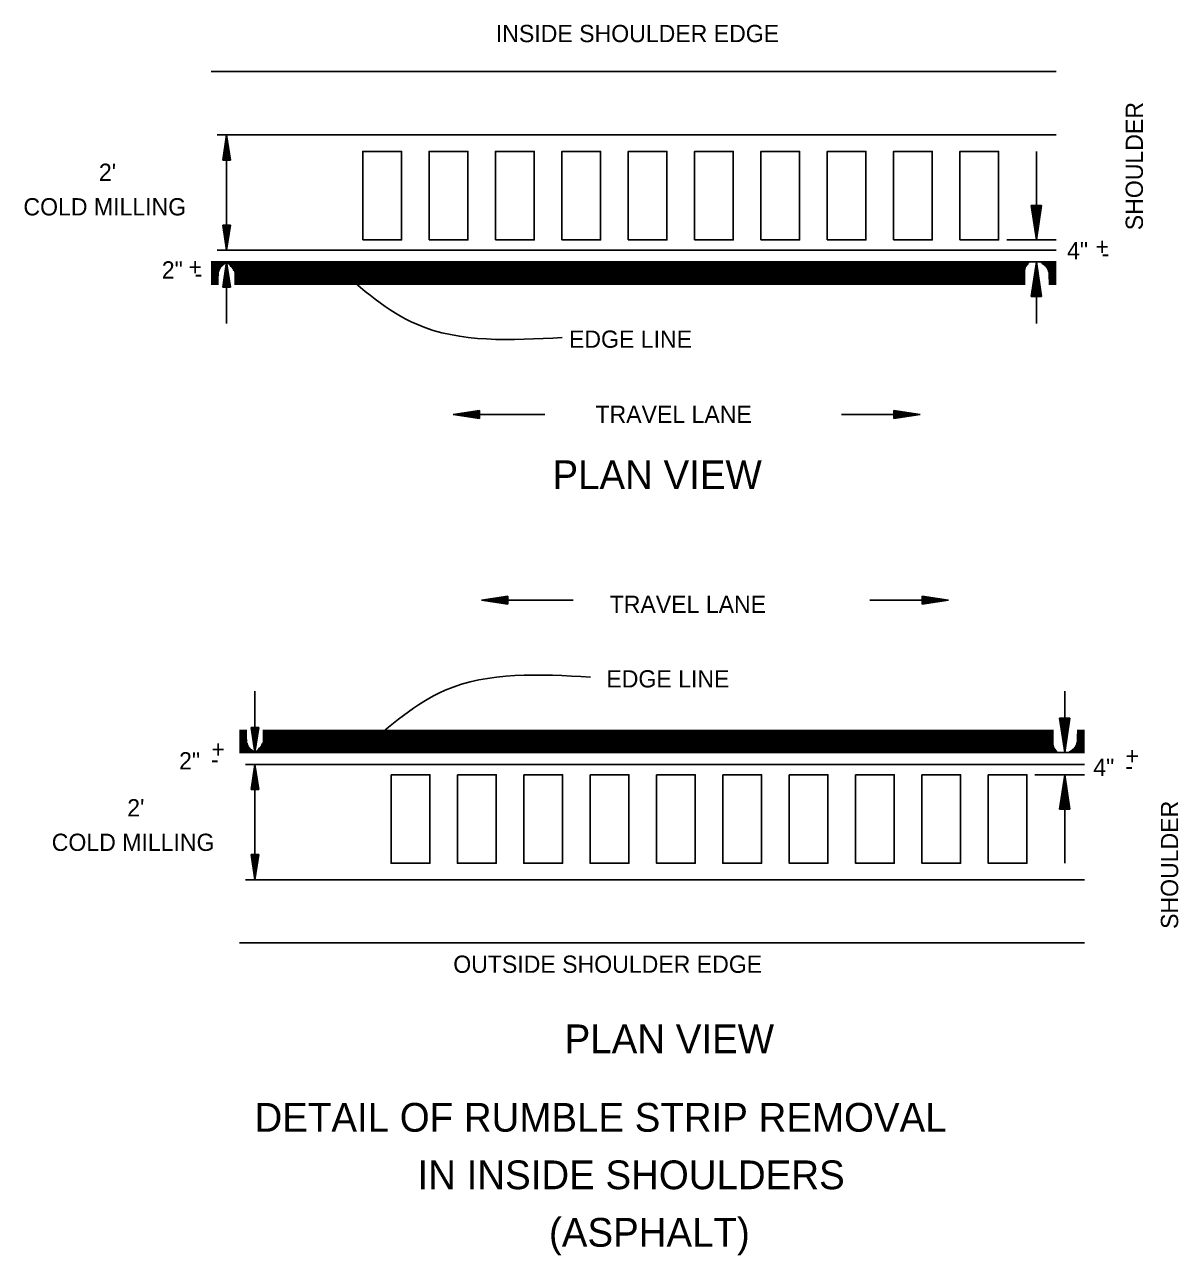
# Model space of a CAD drawing. Extents: x -2842 to 2681, y -2139 to 474.
# Drawn here: x 1152.1 to 1553.5, y -1459 to -1030.9 of the extents above; entities that cross this region are included whole.
import ezdxf

# ---------------------------------------------------------------- set-up
doc = ezdxf.new("R2010")
doc.units = 0
for name, color, linetype in [('B_Copy In', 7, 'Continuous'), ('R_Border', 7, 'Continuous'), ('R_Border Notes', 7, 'Continuous')]:
    doc.layers.add(name, color=color, linetype=linetype)

msp = doc.modelspace()

# ---------------------------------------------------------------- linework, layer by layer
at = {"layer": 'B_Copy In'}
for p, q in [((1216.98, -1047.3), (1510.94, -1047.3)), ((1246.68, -1069.29), (1510.94, -1069.29)), ((1477.46, -1075.05), (1477.46, -1105.81)), ((1246.68, -1109.41), (1510.94, -1109.41)), ((1216.98, -1113.49), (1510.94, -1113.49)), ((1222.31, -1113.72), (1216.98, -1113.72)), ((1221.94, -1113.95), (1216.98, -1113.95)), ((1221.63, -1114.2), (1216.98, -1114.2)), ((1221.25, -1114.44), (1216.98, -1114.44)), ((1221.01, -1114.68), (1216.98, -1114.68)), ((1220.69, -1114.91), (1216.98, -1114.91)), ((1220.52, -1115.17), (1216.98, -1115.17)), ((1220.35, -1115.41), (1216.98, -1115.41)), ((1220.2, -1115.65), (1216.98, -1115.65)), ((1220.13, -1115.89), (1216.98, -1115.89)), ((1220.02, -1116.12), (1216.98, -1116.12)), ((1219.89, -1116.37), (1216.98, -1116.37)), ((1219.87, -1116.61), (1216.98, -1116.61)), ((1219.72, -1116.85), (1216.98, -1116.85)), ((1222.46, -1113.73), (1501.5, -1113.73)), ((1222.79, -1113.97), (1501.28, -1113.97)), ((1223.19, -1114.21), (1501.16, -1114.21)), ((1223.38, -1114.45), (1501, -1114.45)), ((1223.52, -1114.69), (1500.75, -1114.69)), ((1223.65, -1114.92), (1500.58, -1114.92)), ((1223.96, -1115.18), (1500.41, -1115.18)), ((1224.19, -1115.42), (1500.36, -1115.42)), ((1224.36, -1115.66), (1500.27, -1115.66)), ((1224.51, -1115.9), (1500.27, -1115.9)), ((1224.59, -1116.13), (1500.16, -1116.13)), ((1224.69, -1116.38), (1500.14, -1116.38)), ((1224.96, -1116.62), (1500.13, -1116.62)), ((1225.03, -1116.86), (1500.13, -1116.86)), ((1505.61, -1113.73), (1510.94, -1113.73)), ((1505.98, -1113.97), (1510.94, -1113.97)), ((1506.29, -1114.21), (1510.94, -1114.21)), ((1506.67, -1114.45), (1510.94, -1114.45)), ((1506.91, -1114.69), (1510.94, -1114.69)), ((1507.24, -1114.92), (1510.94, -1114.92)), ((1507.4, -1115.18), (1510.94, -1115.18)), ((1507.57, -1115.42), (1510.94, -1115.42)), ((1507.72, -1115.66), (1510.94, -1115.66)), ((1507.79, -1115.9), (1510.94, -1115.9)), ((1507.91, -1116.13), (1510.94, -1116.13)), ((1508.03, -1116.38), (1510.94, -1116.38)), ((1508.06, -1116.62), (1510.94, -1116.62)), ((1508.21, -1116.86), (1510.94, -1116.86)), ((1219.65, -1117.09), (1216.98, -1117.09)), ((1219.65, -1117.33), (1216.98, -1117.33)), ((1219.64, -1117.58), (1216.98, -1117.58)), ((1219.64, -1117.81), (1216.98, -1117.81)), ((1219.62, -1118.05), (1216.98, -1118.05)), ((1219.61, -1118.29), (1216.98, -1118.29)), ((1219.61, -1118.53), (1216.98, -1118.53)), ((1219.6, -1118.78), (1216.98, -1118.78)), ((1219.6, -1119.02), (1216.98, -1119.02)), ((1219.59, -1119.25), (1216.98, -1119.25)), ((1219.58, -1119.49), (1216.98, -1119.49)), ((1219.58, -1119.72), (1216.98, -1119.72)), ((1219.57, -1119.98), (1216.98, -1119.98)), ((1219.57, -1120.21), (1216.98, -1120.21)), ((1219.55, -1120.46), (1216.98, -1120.46)), ((1219.54, -1120.69), (1216.98, -1120.69)), ((1219.54, -1120.93), (1216.98, -1120.93)), ((1219.53, -1121.16), (1216.98, -1121.16)), ((1225.17, -1117.1), (1500.13, -1117.1)), ((1225.17, -1117.35), (1500.13, -1117.35)), ((1225.17, -1117.59), (1500.13, -1117.59)), ((1225.17, -1117.82), (1500.13, -1117.82)), ((1225.17, -1118.06), (1500.13, -1118.06)), ((1225.17, -1118.3), (1500.13, -1118.3)), ((1225.17, -1118.55), (1500.13, -1118.55)), ((1225.17, -1118.79), (1500.13, -1118.79)), ((1225.17, -1119.03), (1500.13, -1119.03)), ((1225.17, -1119.26), (1500.13, -1119.26)), ((1225.17, -1119.5), (1500.13, -1119.5)), ((1225.17, -1119.73), (1500.13, -1119.73)), ((1225.17, -1119.99), (1500.13, -1119.99)), ((1225.17, -1120.22), (1500.13, -1120.22)), ((1225.17, -1120.47), (1500.13, -1120.47)), ((1225.17, -1120.7), (1500.13, -1120.7)), ((1225.17, -1120.95), (1500.13, -1120.95)), ((1225.17, -1121.18), (1500.13, -1121.18)), ((1508.28, -1117.1), (1510.94, -1117.1)), ((1508.28, -1117.35), (1510.94, -1117.35)), ((1508.29, -1117.59), (1510.94, -1117.59)), ((1508.29, -1117.82), (1510.94, -1117.82)), ((1508.3, -1118.06), (1510.94, -1118.06)), ((1508.31, -1118.3), (1510.94, -1118.3)), ((1508.31, -1118.55), (1510.94, -1118.55)), ((1508.32, -1118.79), (1510.94, -1118.79)), ((1508.32, -1119.03), (1510.94, -1119.03)), ((1508.33, -1119.26), (1510.94, -1119.26)), ((1508.35, -1119.5), (1510.94, -1119.5)), ((1508.35, -1119.73), (1510.94, -1119.73)), ((1508.36, -1119.99), (1510.94, -1119.99)), ((1508.36, -1120.22), (1510.94, -1120.22)), ((1508.37, -1120.47), (1510.94, -1120.47)), ((1508.38, -1120.7), (1510.94, -1120.7)), ((1508.38, -1120.95), (1510.94, -1120.95)), ((1508.39, -1121.18), (1510.94, -1121.18)), ((1229.38, -1276.44), (1226.83, -1276.44)), ((1229.39, -1276.67), (1226.83, -1276.67)), ((1229.39, -1276.92), (1226.83, -1276.92)), ((1229.4, -1277.15), (1226.83, -1277.15)), ((1229.41, -1277.4), (1226.83, -1277.4)), ((1229.41, -1277.63), (1226.83, -1277.63)), ((1229.43, -1277.89), (1226.83, -1277.89)), ((1229.43, -1278.12), (1226.83, -1278.12)), ((1229.44, -1278.36), (1226.83, -1278.36)), ((1229.45, -1278.59), (1226.83, -1278.59)), ((1229.45, -1278.83), (1226.83, -1278.83)), ((1229.46, -1279.07), (1226.83, -1279.07)), ((1229.46, -1279.32), (1226.83, -1279.32)), ((1229.47, -1279.56), (1226.83, -1279.56)), ((1235.02, -1276.43), (1509.98, -1276.43)), ((1235.02, -1276.66), (1509.98, -1276.66)), ((1235.02, -1276.9), (1509.98, -1276.9)), ((1235.02, -1277.14), (1509.98, -1277.14)), ((1235.02, -1277.39), (1509.98, -1277.39)), ((1235.02, -1277.62), (1509.98, -1277.62)), ((1235.02, -1277.87), (1509.98, -1277.87)), ((1235.02, -1278.1), (1509.98, -1278.1)), ((1235.02, -1278.35), (1509.98, -1278.35)), ((1235.02, -1278.58), (1509.98, -1278.58)), ((1235.02, -1278.82), (1509.98, -1278.82)), ((1235.02, -1279.06), (1509.98, -1279.06)), ((1235.02, -1279.3), (1509.98, -1279.3)), ((1235.02, -1279.55), (1509.98, -1279.55)), ((1518.15, -1279.55), (1520.79, -1279.55)), ((1518.16, -1279.06), (1520.79, -1279.06)), ((1518.16, -1279.3), (1520.79, -1279.3)), ((1518.17, -1278.58), (1520.79, -1278.58)), ((1518.17, -1278.82), (1520.79, -1278.82)), ((1518.18, -1278.35), (1520.79, -1278.35)), ((1518.19, -1277.87), (1520.79, -1277.87)), ((1518.19, -1278.1), (1520.79, -1278.1)), ((1518.21, -1277.39), (1520.79, -1277.39)), ((1518.21, -1277.62), (1520.79, -1277.62)), ((1518.22, -1277.14), (1520.79, -1277.14)), ((1518.23, -1276.66), (1520.79, -1276.66)), ((1518.23, -1276.9), (1520.79, -1276.9)), ((1518.24, -1276.43), (1520.79, -1276.43)), ((1229.48, -1279.8), (1226.83, -1279.8)), ((1229.48, -1280.03), (1226.83, -1280.03)), ((1229.5, -1280.27), (1226.83, -1280.27)), ((1229.5, -1280.52), (1226.83, -1280.52)), ((1229.56, -1280.76), (1226.83, -1280.76)), ((1229.71, -1281), (1226.83, -1281)), ((1229.74, -1281.24), (1226.83, -1281.24)), ((1229.86, -1281.49), (1226.83, -1281.49)), ((1229.98, -1281.72), (1226.83, -1281.72)), ((1230.05, -1281.96), (1226.83, -1281.96)), ((1230.2, -1282.2), (1226.83, -1282.2)), ((1230.37, -1282.44), (1226.83, -1282.44)), ((1230.53, -1282.7), (1226.83, -1282.7)), ((1230.86, -1282.93), (1226.83, -1282.93)), ((1231.1, -1283.17), (1226.83, -1283.17)), ((1231.48, -1283.41), (1226.83, -1283.41)), ((1231.79, -1283.65), (1226.83, -1283.65)), ((1232.16, -1283.88), (1226.83, -1283.88)), ((1232.31, -1283.87), (1511.35, -1283.87)), ((1232.64, -1283.64), (1511.13, -1283.64)), ((1233.03, -1283.4), (1511, -1283.4)), ((1233.23, -1283.16), (1510.84, -1283.16)), ((1233.37, -1282.92), (1510.6, -1282.92)), ((1233.5, -1282.68), (1510.43, -1282.68)), ((1233.8, -1282.43), (1510.25, -1282.43)), ((1234.04, -1282.19), (1510.21, -1282.19)), ((1234.21, -1281.95), (1510.12, -1281.95)), ((1234.36, -1281.7), (1510.12, -1281.7)), ((1234.44, -1281.47), (1510.01, -1281.47)), ((1234.54, -1281.23), (1509.99, -1281.23)), ((1234.81, -1280.99), (1509.98, -1280.99)), ((1234.88, -1280.75), (1509.98, -1280.75)), ((1235.02, -1279.79), (1509.98, -1279.79)), ((1235.02, -1280.02), (1509.98, -1280.02)), ((1235.02, -1280.26), (1509.98, -1280.26)), ((1235.02, -1280.5), (1509.98, -1280.5)), ((1515.46, -1283.87), (1520.79, -1283.87)), ((1515.83, -1283.64), (1520.79, -1283.64)), ((1516.14, -1283.4), (1520.79, -1283.4)), ((1516.52, -1283.16), (1520.79, -1283.16)), ((1516.76, -1282.92), (1520.79, -1282.92)), ((1517.09, -1282.68), (1520.79, -1282.68)), ((1517.25, -1282.43), (1520.79, -1282.43)), ((1517.42, -1282.19), (1520.79, -1282.19)), ((1517.57, -1281.95), (1520.79, -1281.95)), ((1517.64, -1281.7), (1520.79, -1281.7)), ((1517.76, -1281.47), (1520.79, -1281.47)), ((1517.88, -1281.23), (1520.79, -1281.23)), ((1517.91, -1280.99), (1520.79, -1280.99)), ((1518.06, -1280.75), (1520.79, -1280.75)), ((1518.12, -1280.26), (1520.79, -1280.26)), ((1518.12, -1280.5), (1520.79, -1280.5)), ((1518.14, -1279.79), (1520.79, -1279.79)), ((1518.14, -1280.02), (1520.79, -1280.02)), ((1226.83, -1284.12), (1520.79, -1284.12)), ((1256.53, -1288.2), (1520.79, -1288.2)), ((1256.53, -1328.32), (1520.79, -1328.32)), ((1226.83, -1350.3), (1520.79, -1350.3))]:
    msp.add_line(p, q, dxfattribs=at)
for points in [[(1269.76, -1105.81), (1283.23, -1105.81), (1283.23, -1075.05), (1269.76, -1075.05)], [(1292.83, -1105.81), (1306.31, -1105.81), (1306.31, -1075.05), (1292.83, -1075.05)], [(1315.91, -1105.81), (1329.39, -1105.81), (1329.39, -1075.05), (1315.91, -1075.05)], [(1338.99, -1105.81), (1352.47, -1105.81), (1352.47, -1075.05), (1338.99, -1075.05)], [(1362.07, -1105.81), (1375.54, -1105.81), (1375.54, -1075.05), (1362.07, -1075.05)], [(1385.15, -1105.81), (1398.62, -1105.81), (1398.62, -1075.05), (1385.15, -1075.05)], [(1408.22, -1105.81), (1421.7, -1105.81), (1421.7, -1075.05), (1408.22, -1075.05)], [(1431.3, -1105.81), (1444.78, -1105.81), (1444.78, -1075.05), (1431.3, -1075.05)], [(1454.38, -1105.81), (1467.86, -1105.81), (1467.86, -1075.05), (1454.38, -1075.05)], [(1477.46, -1105.81), (1490.93, -1105.81), (1490.93, -1075.05), (1477.46, -1075.05)], [(1279.6, -1291.8), (1293.08, -1291.8), (1293.08, -1322.56), (1279.6, -1322.56)], [(1302.68, -1291.8), (1316.16, -1291.8), (1316.16, -1322.56), (1302.68, -1322.56)], [(1325.76, -1291.8), (1339.24, -1291.8), (1339.24, -1322.56), (1325.76, -1322.56)], [(1348.84, -1291.8), (1362.32, -1291.8), (1362.32, -1322.56), (1348.84, -1322.56)], [(1371.92, -1291.8), (1385.39, -1291.8), (1385.39, -1322.56), (1371.92, -1322.56)], [(1394.99, -1291.8), (1408.47, -1291.8), (1408.47, -1322.56), (1394.99, -1322.56)], [(1418.07, -1291.8), (1431.55, -1291.8), (1431.55, -1322.56), (1418.07, -1322.56)], [(1441.15, -1291.8), (1454.63, -1291.8), (1454.63, -1322.56), (1441.15, -1322.56)], [(1464.23, -1291.8), (1477.7, -1291.8), (1477.7, -1322.56), (1464.23, -1322.56)], [(1487.3, -1291.8), (1500.78, -1291.8), (1500.78, -1322.56), (1487.3, -1322.56)]]:
    msp.add_lwpolyline(points, close=True, dxfattribs=at)
at = {"layer": 'R_Border Notes'}
for p, q in [((1246.68, -1069.29), (1219.15, -1069.29)), ((1221.06, -1078.06), (1222.38, -1069.29)), ((1222.38, -1069.29), (1222.38, -1109.41)), ((1223.7, -1078.06), (1222.38, -1069.29)), ((1221.27, -1078.06), (1222.38, -1070.74)), ((1221.5, -1078.06), (1222.38, -1072.27)), ((1221.73, -1078.06), (1222.38, -1073.72)), ((1223.49, -1078.06), (1222.38, -1070.74)), ((1223.26, -1078.06), (1222.38, -1072.27)), ((1223.03, -1078.06), (1222.38, -1073.72)), ((1223.7, -1078.06), (1221.06, -1078.06)), ((1221.94, -1078.06), (1222.38, -1075.22)), ((1222.17, -1078.06), (1222.38, -1076.67)), ((1222.8, -1078.06), (1222.38, -1075.22)), ((1222.59, -1078.06), (1222.38, -1076.67)), ((1504.09, -1075.05), (1504.09, -1105.81)), ((1502.29, -1093.81), (1504.09, -1105.81)), ((1502.29, -1093.81), (1505.89, -1093.81)), ((1502.59, -1093.81), (1504.09, -1103.8)), ((1502.89, -1093.81), (1504.09, -1101.75)), ((1503.19, -1093.81), (1504.09, -1099.74)), ((1503.51, -1093.81), (1504.09, -1097.71)), ((1503.81, -1093.81), (1504.09, -1095.7)), ((1505.89, -1093.81), (1504.09, -1105.81)), ((1504.66, -1093.81), (1504.09, -1097.71)), ((1505.29, -1093.81), (1504.09, -1101.75)), ((1505.59, -1093.81), (1504.09, -1103.8)), ((1504.99, -1093.81), (1504.09, -1099.74)), ((1504.36, -1093.81), (1504.09, -1095.7)), ((1221.06, -1100.64), (1222.38, -1109.41)), ((1221.06, -1100.64), (1223.7, -1100.64)), ((1221.27, -1100.64), (1222.38, -1107.96)), ((1221.5, -1100.64), (1222.38, -1106.43)), ((1221.73, -1100.64), (1222.38, -1104.98)), ((1221.96, -1100.64), (1222.38, -1103.48)), ((1222.17, -1100.64), (1222.38, -1102.03)), ((1223.7, -1100.64), (1222.38, -1109.41)), ((1222.82, -1100.64), (1222.38, -1103.48)), ((1223.26, -1100.64), (1222.38, -1106.43)), ((1223.49, -1100.64), (1222.38, -1107.96)), ((1223.03, -1100.64), (1222.38, -1104.98)), ((1222.59, -1100.64), (1222.38, -1102.03)), ((1493.73, -1105.81), (1510.94, -1105.81)), ((1246.68, -1109.41), (1219.15, -1109.41)), ((1221.06, -1122.26), (1222.38, -1113.49)), ((1221.27, -1122.26), (1222.38, -1114.95)), ((1221.5, -1122.26), (1222.38, -1116.47)), ((1223.7, -1122.26), (1222.38, -1113.49)), ((1222.38, -1113.49), (1222.38, -1134.86)), ((1223.49, -1122.26), (1222.38, -1114.95)), ((1223.26, -1122.26), (1222.38, -1116.47)), ((1502.29, -1125.49), (1504.09, -1113.49)), ((1502.59, -1125.49), (1504.09, -1115.5)), ((1505.89, -1125.49), (1504.09, -1113.49)), ((1504.09, -1113.49), (1504.09, -1134.86)), ((1505.59, -1125.49), (1504.09, -1115.5)), ((1221.73, -1122.26), (1222.38, -1117.92)), ((1221.94, -1122.26), (1222.38, -1119.42)), ((1222.17, -1122.26), (1222.38, -1120.88)), ((1223.03, -1122.26), (1222.38, -1117.92)), ((1222.8, -1122.26), (1222.38, -1119.42)), ((1222.59, -1122.26), (1222.38, -1120.88)), ((1502.89, -1125.49), (1504.09, -1117.55)), ((1503.19, -1125.49), (1504.09, -1119.56)), ((1505.29, -1125.49), (1504.09, -1117.55)), ((1504.99, -1125.49), (1504.09, -1119.56)), ((1223.7, -1122.26), (1221.06, -1122.26)), ((1505.89, -1125.49), (1502.29, -1125.49)), ((1503.51, -1125.49), (1504.09, -1121.59)), ((1503.81, -1125.49), (1504.09, -1123.6)), ((1504.66, -1125.49), (1504.09, -1121.59)), ((1504.36, -1125.49), (1504.09, -1123.6)), ((1310.37, -1165.14), (1301.14, -1166.53)), ((1301.14, -1166.53), (1333.12, -1166.53)), ((1310.37, -1167.91), (1301.14, -1166.53)), ((1310.37, -1165.37), (1302.69, -1166.53)), ((1310.37, -1167.68), (1302.69, -1166.53)), ((1310.37, -1165.61), (1304.27, -1166.53)), ((1310.37, -1167.45), (1304.27, -1166.53)), ((1310.37, -1165.84), (1305.8, -1166.53)), ((1310.37, -1167.22), (1305.8, -1166.53)), ((1310.37, -1166.08), (1307.37, -1166.53)), ((1310.37, -1166.98), (1307.37, -1166.53)), ((1310.37, -1166.31), (1308.92, -1166.53)), ((1310.37, -1166.75), (1308.92, -1166.53)), ((1310.37, -1165.14), (1310.37, -1167.91)), ((1436.31, -1166.52), (1463.68, -1166.52)), ((1454.45, -1165.13), (1463.68, -1166.52)), ((1454.45, -1167.9), (1454.45, -1165.13)), ((1454.45, -1165.36), (1462.13, -1166.52)), ((1454.45, -1165.59), (1460.55, -1166.52)), ((1454.45, -1165.82), (1459.02, -1166.52)), ((1454.45, -1166.07), (1457.45, -1166.52)), ((1454.45, -1166.3), (1455.9, -1166.52)), ((1454.45, -1167.9), (1463.68, -1166.52)), ((1454.45, -1166.97), (1457.45, -1166.52)), ((1454.45, -1167.44), (1460.55, -1166.52)), ((1454.45, -1167.67), (1462.13, -1166.52)), ((1454.45, -1167.21), (1459.02, -1166.52)), ((1454.45, -1166.74), (1455.9, -1166.52)), ((1320.22, -1229.7), (1310.99, -1231.08)), ((1310.99, -1231.08), (1342.96, -1231.08)), ((1320.22, -1232.46), (1310.99, -1231.08)), ((1320.22, -1229.93), (1312.54, -1231.08)), ((1320.22, -1232.23), (1312.54, -1231.08)), ((1320.22, -1230.16), (1314.12, -1231.08)), ((1320.22, -1232), (1314.12, -1231.08)), ((1320.22, -1230.39), (1315.65, -1231.08)), ((1320.22, -1231.77), (1315.65, -1231.08)), ((1320.22, -1230.63), (1317.22, -1231.08)), ((1320.22, -1231.53), (1317.22, -1231.08)), ((1320.22, -1230.86), (1318.77, -1231.08)), ((1320.22, -1231.3), (1318.77, -1231.08)), ((1320.22, -1232.46), (1320.22, -1229.7)), ((1446.16, -1231.09), (1473.53, -1231.09)), ((1464.3, -1229.71), (1473.53, -1231.09)), ((1464.3, -1229.71), (1464.3, -1232.48)), ((1464.3, -1229.94), (1471.98, -1231.09)), ((1464.3, -1230.17), (1470.4, -1231.09)), ((1464.3, -1230.4), (1468.86, -1231.09)), ((1464.3, -1230.64), (1467.3, -1231.09)), ((1464.3, -1230.87), (1465.75, -1231.09)), ((1464.3, -1232.48), (1473.53, -1231.09)), ((1464.3, -1231.54), (1467.3, -1231.09)), ((1464.3, -1232.01), (1470.4, -1231.09)), ((1464.3, -1232.24), (1471.98, -1231.09)), ((1464.3, -1231.78), (1468.86, -1231.09)), ((1464.3, -1231.31), (1465.75, -1231.09)), ((1232.23, -1284.12), (1232.23, -1262.75)), ((1513.94, -1284.12), (1513.94, -1262.75)), ((1230.91, -1275.35), (1232.23, -1284.12)), ((1233.54, -1275.35), (1230.91, -1275.35)), ((1231.12, -1275.35), (1232.23, -1282.66)), ((1231.35, -1275.35), (1232.23, -1281.14)), ((1231.58, -1275.35), (1232.23, -1279.69)), ((1231.79, -1275.35), (1232.23, -1278.19)), ((1232.02, -1275.35), (1232.23, -1276.73)), ((1233.54, -1275.35), (1232.23, -1284.12)), ((1232.64, -1275.35), (1232.23, -1278.19)), ((1233.11, -1275.35), (1232.23, -1281.14)), ((1233.34, -1275.35), (1232.23, -1282.66)), ((1232.87, -1275.35), (1232.23, -1279.69)), ((1232.44, -1275.35), (1232.23, -1276.73)), ((1512.14, -1272.12), (1513.94, -1284.12)), ((1515.74, -1272.12), (1512.14, -1272.12)), ((1512.44, -1272.12), (1513.94, -1282.11)), ((1512.74, -1272.12), (1513.94, -1280.05)), ((1513.04, -1272.12), (1513.94, -1278.05)), ((1513.36, -1272.12), (1513.94, -1276.02)), ((1513.66, -1272.12), (1513.94, -1274.01)), ((1515.74, -1272.12), (1513.94, -1284.12)), ((1514.51, -1272.12), (1513.94, -1276.02)), ((1515.14, -1272.12), (1513.94, -1280.05)), ((1515.44, -1272.12), (1513.94, -1282.11)), ((1514.84, -1272.12), (1513.94, -1278.05)), ((1514.21, -1272.12), (1513.94, -1274.01)), ((1256.53, -1288.2), (1229, -1288.2)), ((1230.91, -1296.97), (1232.23, -1288.2)), ((1233.54, -1296.97), (1232.23, -1288.2)), ((1232.23, -1328.32), (1232.23, -1288.2)), ((1231.12, -1296.97), (1232.23, -1289.65)), ((1231.35, -1296.97), (1232.23, -1291.17)), ((1233.34, -1296.97), (1232.23, -1289.65)), ((1233.11, -1296.97), (1232.23, -1291.17)), ((1503.57, -1291.8), (1520.79, -1291.8)), ((1512.14, -1303.8), (1513.94, -1291.8)), ((1515.74, -1303.8), (1513.94, -1291.8)), ((1513.94, -1322.56), (1513.94, -1291.8)), ((1231.58, -1296.97), (1232.23, -1292.63)), ((1231.81, -1296.97), (1232.23, -1294.13)), ((1232.02, -1296.97), (1232.23, -1295.58)), ((1232.87, -1296.97), (1232.23, -1292.63)), ((1232.67, -1296.97), (1232.23, -1294.13)), ((1232.44, -1296.97), (1232.23, -1295.58)), ((1512.44, -1303.8), (1513.94, -1293.81)), ((1512.74, -1303.8), (1513.94, -1295.86)), ((1515.44, -1303.8), (1513.94, -1293.81)), ((1515.14, -1303.8), (1513.94, -1295.86)), ((1230.91, -1296.97), (1233.54, -1296.97)), ((1513.04, -1303.8), (1513.94, -1297.87)), ((1513.36, -1303.8), (1513.94, -1299.9)), ((1514.84, -1303.8), (1513.94, -1297.87)), ((1514.51, -1303.8), (1513.94, -1299.9)), ((1512.14, -1303.8), (1515.74, -1303.8)), ((1513.66, -1303.8), (1513.94, -1301.91)), ((1514.21, -1303.8), (1513.94, -1301.91)), ((1230.91, -1319.55), (1232.23, -1328.32)), ((1233.54, -1319.55), (1230.91, -1319.55)), ((1231.12, -1319.55), (1232.23, -1326.87)), ((1231.35, -1319.55), (1232.23, -1325.34)), ((1231.58, -1319.55), (1232.23, -1323.89)), ((1231.79, -1319.55), (1232.23, -1322.39)), ((1232.02, -1319.55), (1232.23, -1320.93)), ((1233.54, -1319.55), (1232.23, -1328.32)), ((1232.64, -1319.55), (1232.23, -1322.39)), ((1233.11, -1319.55), (1232.23, -1325.34)), ((1233.34, -1319.55), (1232.23, -1326.87)), ((1232.87, -1319.55), (1232.23, -1323.89)), ((1232.44, -1319.55), (1232.23, -1320.93)), ((1256.53, -1328.32), (1229, -1328.32))]:
    msp.add_line(p, q, dxfattribs=at)
for points in [[(1339.14, -1139.79), (1288.52, -1135.16), (1260.5, -1115.08)], [(1348.99, -1257.82), (1298.37, -1262.45), (1270.35, -1282.52)]]:
    msp.add_spline(points, degree=3, dxfattribs=at)

# ---------------------------------------------------------------- texts
at = {"layer": 'R_Border'}
for s, height, p in [('INSIDE SHOULDER EDGE', 6, (1316.04, -1037.04)), ("2'", 6, (1177.95, -1085.3)), ('COLD MILLING', 6, (1151.7, -1097.3)), ('4"', 6, (1514.72, -1112.55)), ('2"', 6, (1199.84, -1119.25)), ('EDGE LINE', 6, (1341.47, -1143.33)), ('TRAVEL LANE', 6, (1350.68, -1169.45)), ('PLAN VIEW', 10, (1335.72, -1192.48)), ('PLAN VIEW', 10, (1339.97, -1388.65)), ('DETAIL OF RUMBLE STRIP REMOVAL', 10, (1232.08, -1415.94)), ('IN INSIDE SHOULDERS', 10, (1288.78, -1435.94)), ('(ASPHALT)', 10, (1334.52, -1455.94))]:
    msp.add_text(s, height=height, dxfattribs=at).set_placement(p)
for s, rotation, p in [('SHOULDER', 90, (1541.12, -1102.45)), ('+', 179.6189, (1529.31, -1105.33)), ('-', 179.6189, (1529.41, -1108.86)), ('+', 180, (1213.79, -1112.38)), ('-', 180, (1213.92, -1115.91)), ('TRAVEL LANE', 360, (1355.63, -1235.55)), ('EDGE LINE', 360, (1354.48, -1261.46)), ('2"', 360, (1205.85, -1289.96)), ('+', 360, (1217.09, -1285.95)), ('+', 360, (1535.08, -1288.22)), ('-', 360, (1216.96, -1289.48)), ('4"', 360, (1523.85, -1292.23)), ('-', 360, (1534.96, -1291.75)), ("2'", 360, (1187.8, -1306.3)), ('SHOULDER', 90, (1553.38, -1345.43)), ('COLD MILLING', 360, (1161.55, -1318.3)), ('OUTSIDE SHOULDER EDGE', 360, (1301.22, -1360.69))]:
    msp.add_text(s, height=6, rotation=rotation, dxfattribs=at).set_placement(p)

doc.saveas('drawing.dxf')
